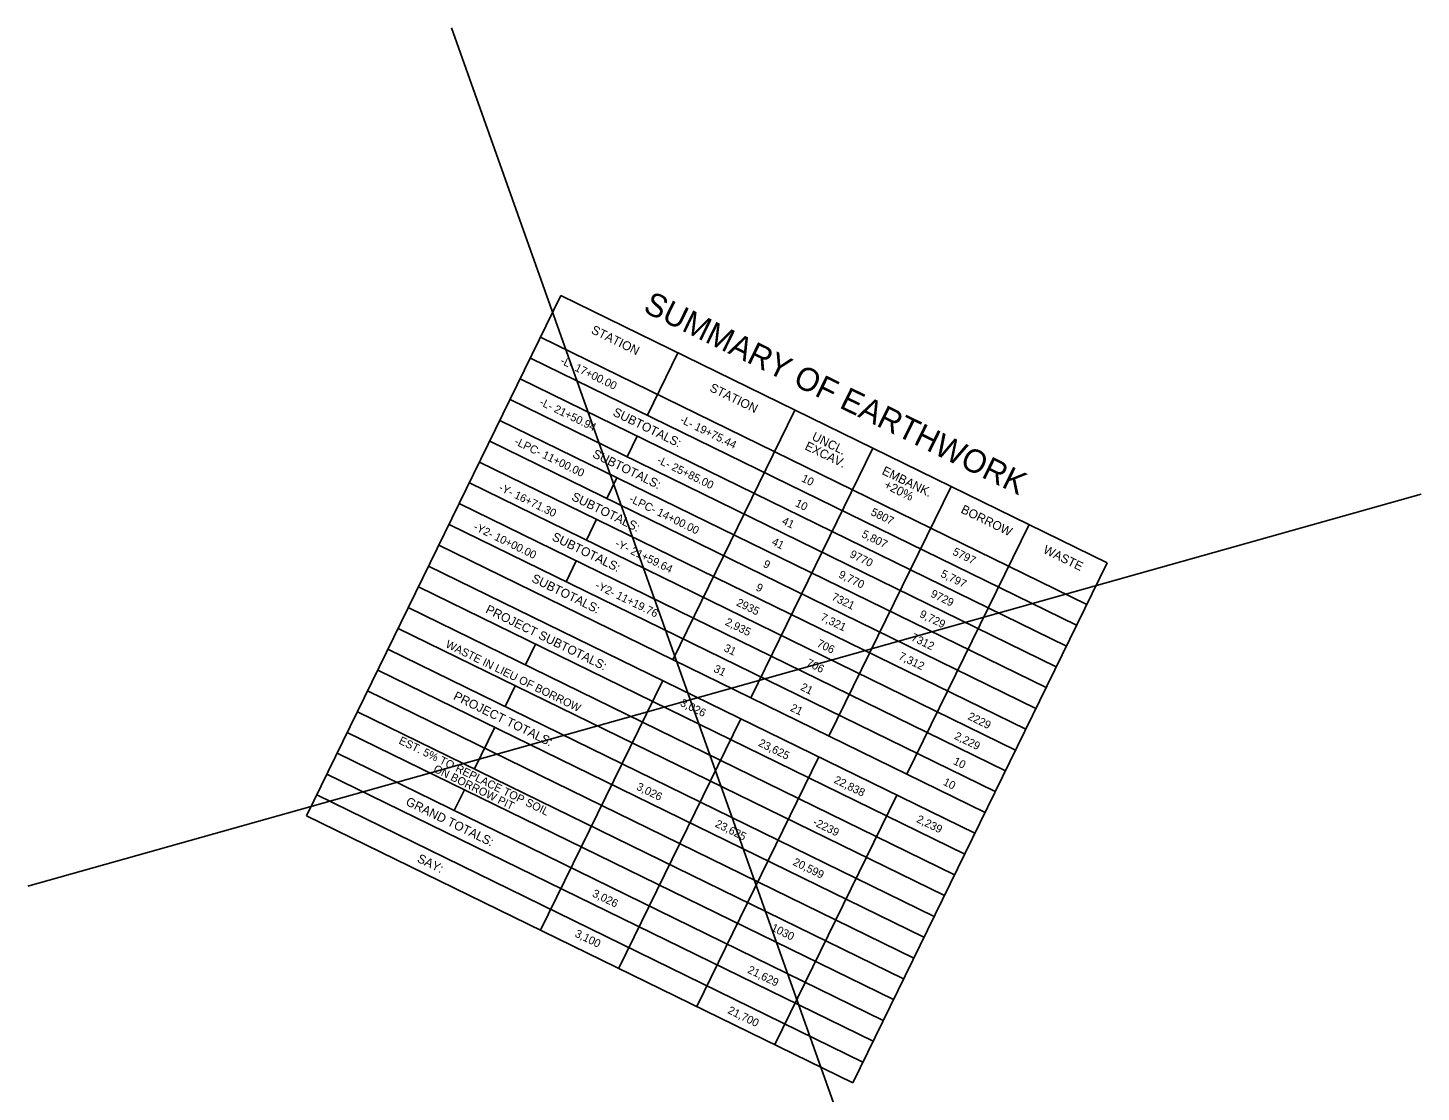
# Model space of a CAD drawing. Extents: x 1523741 to 1527628, y 632733 to 635404.
# Drawn here: x 1526254 to 1527006, y 634429 to 635003 of the extents above; entities that cross this region are included whole.
import ezdxf

# ---------------------------------------------------------------- set-up
doc = ezdxf.new("R2010")
doc.units = 0
for name, color, linetype in [('Scratch_Level_0', 7, 'Continuous'), ('Sheet Summary Combination CELL', 7, 'Continuous'), ('Sheet Summary Combination Grid CELL', 7, 'Continuous')]:
    doc.layers.add(name, color=color, linetype=linetype)

msp = doc.modelspace()

# ---------------------------------------------------------------- linework, layer by layer
at = {"layer": 'Scratch_Level_0'}
for p, q in [((1526483.1, 635003.21), (1526731.38, 634304.38)), ((1526254.32, 634539.87), (1527006.5, 634751.57))]:
    msp.add_line(p, q, dxfattribs=at)
at = {"layer": 'Sheet Summary Combination CELL'}
for p, q in [((1526626.83, 634817.16), (1526626.83, 634817.16)), ((1526632.4, 634814.33), (1526632.4, 634814.33)), ((1526640.62, 634810.53), (1526640.62, 634810.53)), ((1526645.6, 634807.98), (1526645.6, 634807.98))]:
    msp.add_line(p, q, dxfattribs=at)
at = {"layer": 'Sheet Summary Combination Grid CELL'}
for p, q in [((1526542.09, 634858.66), (1526404.8, 634577.94)), ((1526542.09, 634858.66), (1526836.97, 634714.44)), ((1526531.11, 634836.2), (1526825.98, 634691.99)), ((1526525.62, 634824.97), (1526820.49, 634680.76)), ((1526605.29, 634827.75), (1526588.81, 634794.07)), ((1526520.13, 634813.74), (1526815, 634669.53)), ((1526514.63, 634802.52), (1526809.51, 634658.3)), ((1526668.44, 634796.87), (1526602.54, 634662.12)), ((1526509.14, 634791.29), (1526804.02, 634647.07)), ((1526503.65, 634780.06), (1526798.52, 634635.84)), ((1526583.32, 634782.84), (1526577.83, 634771.61)), ((1526710.57, 634776.26), (1526644.67, 634641.51)), ((1526498.16, 634768.83), (1526793.03, 634624.61)), ((1526498.16, 634768.83), (1526793.03, 634624.61)), ((1526492.67, 634757.6), (1526787.54, 634613.38)), ((1526572.34, 634760.38), (1526566.85, 634749.15)), ((1526752.7, 634755.66), (1526686.8, 634620.91)), ((1526487.18, 634746.37), (1526782.05, 634602.16)), ((1526481.68, 634735.14), (1526776.56, 634590.93)), ((1526561.36, 634737.92), (1526555.86, 634726.69)), ((1526794.84, 634735.05), (1526728.93, 634600.3)), ((1526476.19, 634723.91), (1526771.06, 634579.7)), ((1526470.7, 634712.68), (1526765.57, 634568.47)), ((1526550.37, 634715.46), (1526544.88, 634704.23)), ((1526836.97, 634714.44), (1526699.67, 634433.72)), ((1526465.21, 634701.46), (1526760.08, 634557.24)), ((1526459.72, 634690.23), (1526754.59, 634546.01)), ((1526454.22, 634679), (1526749.1, 634534.78)), ((1526448.73, 634667.77), (1526743.6, 634523.55)), ((1526528.4, 634670.55), (1526522.91, 634659.32)), ((1526443.24, 634656.54), (1526738.11, 634512.32)), ((1526597.05, 634650.89), (1526531.15, 634516.14)), ((1526437.75, 634645.31), (1526732.62, 634501.09)), ((1526517.42, 634648.09), (1526511.93, 634636.86)), ((1526432.26, 634634.08), (1526727.13, 634489.87)), ((1526639.18, 634630.28), (1526573.28, 634495.54)), ((1526426.76, 634622.85), (1526721.64, 634478.64)), ((1526506.44, 634625.63), (1526495.45, 634603.17)), ((1526421.27, 634611.62), (1526716.15, 634467.41)), ((1526681.31, 634609.68), (1526615.41, 634474.93)), ((1526415.78, 634600.39), (1526710.65, 634456.18)), ((1526410.29, 634589.17), (1526705.16, 634444.95)), ((1526489.96, 634591.94), (1526484.47, 634580.72)), ((1526723.44, 634589.07), (1526657.54, 634454.33)), ((1526404.8, 634577.94), (1526699.67, 634433.72))]:
    msp.add_line(p, q, dxfattribs=at)

# ---------------------------------------------------------------- texts
at = {"layer": 'Sheet Summary Combination CELL'}
for s, height, rotation, p in [('SUMMARY OF EARTHWORK', 12.5001, 333.94965, (1526585.91, 634850.22)), ('STATION', 4.8, 333.93772, (1526558.04, 634838.57)), ('-L- 17+00.00', 4.32, 333.93772, (1526541.38, 634822.16)), ('STATION', 4.8, 333.93772, (1526621.95, 634807.33)), ('-L- 21+50.94', 4.32, 333.93772, (1526530.18, 634799.81)), ('SUBTOTALS:', 4.8, 333.93772, (1526569.73, 634794.15)), ('-L- 19+75.44', 4.32, 333.93772, (1526606.01, 634790.31)), ('UNCL.', 4.8, 333.93772, (1526677.16, 634781.02)), ('-LPC- 11+00.00', 4.32, 333.93772, (1526516.63, 634778.61)), ('EXCAV.', 4.8, 333.93772, (1526673.36, 634775.87)), ('SUBTOTALS:', 4.8, 333.93772, (1526558.72, 634771.65)), ('-L- 25+85.00', 4.32, 333.93772, (1526593.65, 634768.53)), ('EMBANK.', 4.8, 333.93772, (1526714.99, 634762.52)), ('-Y- 16+71.30', 4.32, 333.93772, (1526508.17, 634753.68)), ('10', 4.32, 333.93772, (1526671.58, 634758.57)), ('+20%', 4.8, 333.93772, (1526716.05, 634754.99)), ('SUBTOTALS:', 4.8, 333.93772, (1526547.41, 634748.53)), ('-LPC- 14+00.00', 4.32, 333.93772, (1526578.59, 634747.62)), ('10', 4.32, 333.93772, (1526668.22, 634745.21)), ('5807', 4.32, 333.93772, (1526709, 634740.43)), ('BORROW', 4.8, 333.93772, (1526757.61, 634741.67)), ('-Y2- 10+00.00', 4.32, 333.93772, (1526494.52, 634732.52)), ('41', 4.32, 333.93772, (1526661.01, 634735.63)), ('5,807', 4.32, 333.93772, (1526704.11, 634728.52)), ('SUBTOTALS:', 4.8, 333.93772, (1526536.83, 634726.88)), ('-Y- 21+59.64', 4.32, 333.93772, (1526570.97, 634723.52)), ('41', 4.32, 333.93772, (1526655.52, 634724.4)), ('9770', 4.32, 333.93772, (1526697.65, 634717.71)), ('5797', 4.32, 333.93772, (1526753.19, 634719.01)), ('WASTE', 4.8, 333.93772, (1526802.03, 634719.95)), ('9', 4.32, 333.93772, (1526650.89, 634712.42)), ('9,770', 4.32, 333.93772, (1526691.64, 634706.74)), ('5,797', 4.32, 333.93772, (1526746.73, 634707.1)), ('SUBTOTALS:', 4.8, 333.93772, (1526525.84, 634704.42)), ('-Y2- 11+19.76', 4.32, 333.93772, (1526560.23, 634700.94)), ('9', 4.32, 333.93772, (1526646.94, 634699.79)), ('2935', 4.32, 333.93772, (1526636.42, 634691.56)), ('7321', 4.32, 333.93772, (1526687.83, 634694.65)), ('9729', 4.32, 333.93772, (1526741.34, 634696.34)), ('PROJECT SUBTOTALS:', 4.8, 333.93772, (1526501.01, 634687.72)), ('7,321', 4.32, 333.93772, (1526681.82, 634683.69)), ('9,729', 4.32, 333.93772, (1526735.33, 634685.37)), ('2,935', 4.32, 333.93772, (1526630.38, 634681.08)), ('WASTE IN LIEU OF BORROW', 4.32, 333.93772, (1526479.45, 634669.06)), ('706', 4.32, 333.93772, (1526679.9, 634669.5)), ('7312', 4.32, 333.93772, (1526730.83, 634672.75)), ('31', 4.32, 333.93772, (1526629.64, 634667.04)), ('7,312', 4.32, 333.93772, (1526724.02, 634662.68)), ('31', 4.32, 333.93772, (1526624.15, 634655.81)), ('706', 4.32, 333.93772, (1526674.23, 634659.05)), ('21', 4.32, 333.93772, (1526671.06, 634645.99)), ('PROJECT TOTALS:', 4.8, 333.93772, (1526483.65, 634640.94)), ('3,026', 4.32, 333.93772, (1526606.07, 634637.45)), ('21', 4.32, 333.93772, (1526665.56, 634634.76)), ('2229', 4.32, 333.93772, (1526761.36, 634630.16)), ('EST. 5% TO REPLACE TOP SOIL', 4.32, 333.93772, (1526454.18, 634617.05)), ('23,625', 4.32, 333.93772, (1526648.32, 634615.78)), ('2,229', 4.32, 333.93772, (1526754.1, 634619.58)), (' ON BORROW PIT', 4.32, 333.93772, (1526471.46, 634602.5)), ('10', 4.32, 333.93772, (1526753.53, 634605.95)), ('22,838', 4.32, 333.93772, (1526689.09, 634595.84)), ('10', 4.32, 333.93772, (1526748.04, 634594.72)), ('3,026', 4.32, 333.93772, (1526582.48, 634592.19)), ('GRAND TOTALS:', 4.8, 333.93772, (1526457.89, 634583.94)), ('23,625', 4.32, 333.93772, (1526624.95, 634572.15)), ('-2239', 4.32, 333.93772, (1526677.72, 634573.11)), ('2,239', 4.32, 333.93772, (1526733.68, 634574.66)), ('SAY:', 4.8, 333.93772, (1526464.09, 634553.23)), ('20,599', 4.32, 333.93772, (1526666.94, 634551.53)), ('3,026', 4.32, 333.93772, (1526558.68, 634534.54)), ('3,100', 4.32, 333.93772, (1526549.22, 634512.88)), ('1030', 4.32, 333.93772, (1526655.2, 634516.07)), ('21,629', 4.32, 333.93772, (1526642.47, 634493.34)), ('21,700', 4.32, 333.93772, (1526631.78, 634471.49))]:
    msp.add_text(s, height=height, rotation=rotation, dxfattribs=at).set_placement(p)

doc.saveas('drawing.dxf')
